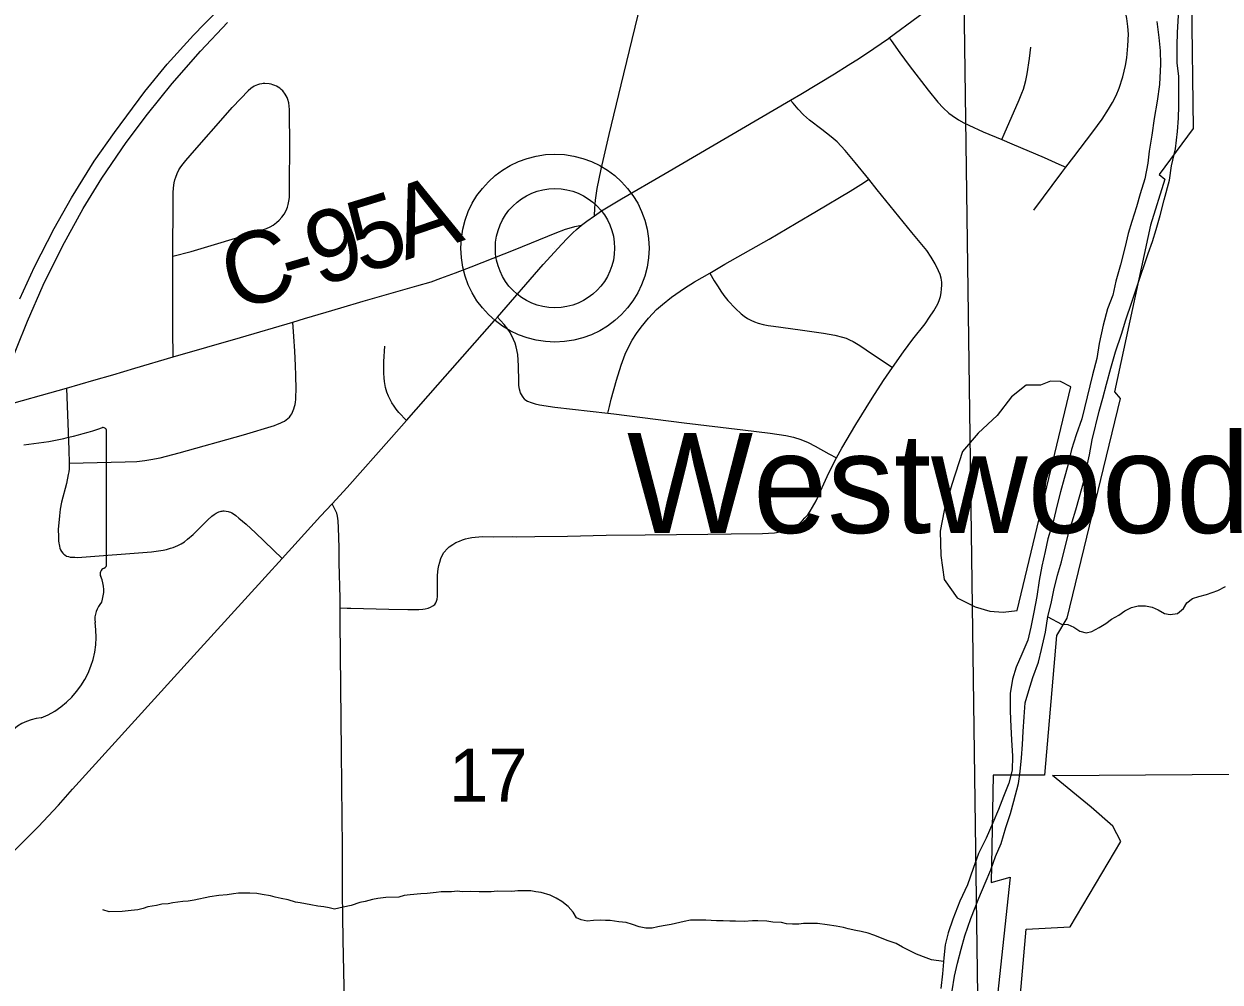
# Model space of a CAD drawing. Extents: x 0 to 34, y 0 to 22.
# Drawn here: x 7.165 to 8.111, y 18.473 to 19.232 of the extents above; entities that cross this region are included whole.
import ezdxf

# ---------------------------------------------------------------- set-up
doc = ezdxf.new("R2010")
doc.units = 0
for name, color, linetype in [('GM_X_County_Road', 7, 'Continuous'), ('GM_X_County_Road_Text', 7, 'Continuous'), ('GM_X_Major_River', 7, 'Continuous'), ('GM_X_Minor_Lake', 7, 'Continuous'), ('GM_X_Minor_River', 7, 'Continuous'), ('GM_X_Section', 7, 'Continuous'), ('GM_X_Section_Text', 7, 'Continuous'), ('GM_X_State_Route', 7, 'Continuous'), ('GM_X_State_Shield', 7, 'Continuous'), ('GM_X_Township_Road', 7, 'Continuous'), ('GM_X_Unincorporated', 7, 'Continuous'), ('GM_X_Unincorporated_Location', 7, 'Continuous'), ('GM_X_Unincorporated_Text', 7, 'Continuous')]:
    doc.layers.add(name, color=color, linetype=linetype)

msp = doc.modelspace()

# ---------------------------------------------------------------- linework, layer by layer
at = {"layer": 'GM_X_County_Road'}
msp.add_line((7.13975, 18.92718), (7.19837, 18.94339), dxfattribs=at)
for points in [[(7.61596, 19.07986), (7.61634, 19.08595), (7.61673, 19.09225), (7.61814, 19.10156), (7.62132, 19.11684), (7.62769, 19.14418), (7.63728, 19.18355), (7.65046, 19.23785), (7.65951, 19.27714)], [(7.8493, 19.2208), (7.87219, 19.23783), (7.90225, 19.25991), (7.91163, 19.26642), (7.92009, 19.2719), (7.92362, 19.27405)], [(7.77107, 19.17149), (7.77918, 19.17624), (7.80601, 19.19233), (7.81679, 19.19922), (7.82563, 19.20472), (7.83706, 19.21235), (7.84864, 19.22032), (7.8493, 19.2208)], [(7.61596, 19.07986), (7.62162, 19.08382), (7.63756, 19.09343), (7.67204, 19.11347), (7.77107, 19.17149)], [(7.60583, 19.07256), (7.6101, 19.07574), (7.61596, 19.07986)], [(7.37735, 18.99585), (7.38665, 18.99858), (7.40378, 19.0037), (7.41538, 19.00708), (7.43309, 19.01225), (7.47539, 19.02448), (7.48687, 19.0278), (7.49452, 19.03049), (7.5061, 19.0347), (7.51859, 19.03956), (7.55332, 19.05339), (7.58502, 19.06625), (7.5932, 19.06928), (7.59776, 19.07073), (7.60053, 19.07143), (7.60583, 19.07256)], [(7.53937, 18.99983), (7.57544, 19.04144), (7.5901, 19.05753), (7.59438, 19.06204), (7.59646, 19.06401), (7.59893, 19.06637), (7.60186, 19.06911), (7.60583, 19.07256)], [(7.28287, 18.96823), (7.336, 18.98369), (7.37735, 18.99585)], [(7.46732, 18.91785), (7.49216, 18.94611), (7.53698, 18.99707), (7.53937, 18.99983)], [(7.19837, 18.94339), (7.22009, 18.94977), (7.23495, 18.95406), (7.25249, 18.95937), (7.28287, 18.96823)], [(7.40851, 18.85201), (7.42041, 18.86491), (7.45543, 18.90433), (7.46732, 18.91785)], [(7.3689, 18.80869), (7.39939, 18.84211), (7.40851, 18.85201)], [(6.91432, 18.35384), (6.92169, 18.36116), (7.00322, 18.43572), (7.06045, 18.4882), (7.09027, 18.5154), (7.15409, 18.57432), (7.16355, 18.58378), (7.17608, 18.59615), (7.19198, 18.61337), (7.20324, 18.62595), (7.29913, 18.73183), (7.35546, 18.79395), (7.3689, 18.80869)]]:
    msp.add_lwpolyline(points, dxfattribs=at)
at = {"layer": 'GM_X_Major_River'}
for points in [[(7.89913, 18.46638), (7.90094, 18.47815), (7.90314, 18.48841), (7.90609, 18.49943), (7.90905, 18.51007), (7.91388, 18.52376), (7.92021, 18.53974), (7.92505, 18.55153), (7.92952, 18.56218), (7.93324, 18.57283), (7.93771, 18.5831), (7.94141, 18.59565), (7.94512, 18.60667), (7.94771, 18.61655), (7.9514, 18.63061), (7.95285, 18.6401), (7.95391, 18.65073), (7.95459, 18.66136), (7.95528, 18.6716), (7.95596, 18.68336), (7.95664, 18.69436), (7.9596, 18.70425), (7.96293, 18.71451), (7.9674, 18.72668), (7.9696, 18.73656), (7.97292, 18.75024), (7.97472, 18.76276), (7.9773, 18.77302), (7.9795, 18.78366), (7.98245, 18.79544), (7.98541, 18.80608), (7.98835, 18.81786), (7.99094, 18.82812), (7.99687, 18.84712), (7.99982, 18.85739), (8.00278, 18.86879), (8.00535, 18.8798), (8.00755, 18.89082), (8.00974, 18.90259), (8.01526, 18.92539), (8.01822, 18.93565), (8.02117, 18.94667), (8.0245, 18.95921), (8.0282, 18.97213), (8.03302, 18.9862), (8.03635, 18.9976), (8.04118, 19.01167), (8.04526, 19.02421), (8.05417, 19.05007), (8.05751, 19.05958), (8.06048, 19.06908), (8.06343, 19.0801), (8.06675, 19.09264), (8.07081, 19.10822), (8.07263, 19.11961), (8.07557, 19.13291), (8.07736, 19.14657), (8.07805, 19.1572), (8.07836, 19.16706), (8.0782, 19.19057), (8.07699, 19.2008), (8.07689, 19.21483), (8.0772, 19.22507), (8.07822, 19.24289)], [(8.06086, 19.23368), (8.06246, 19.22117), (8.06367, 19.21056), (8.06374, 19.19994), (8.06309, 19.18401), (8.06129, 19.17072), (8.05873, 19.15705), (8.05693, 19.14376), (8.05475, 19.13123), (8.05368, 19.12174), (8.05149, 19.10921), (8.04778, 19.09743), (8.04482, 19.08717), (8.04112, 19.07538), (8.03815, 19.06588), (8.03595, 19.05562), (8.03226, 19.04118), (8.02857, 19.02826)], [(8.02857, 19.02826), (8.02599, 19.01724), (8.0219, 19.00621), (8.01858, 18.9933), (8.01527, 18.97886), (8.01346, 18.96709), (8.01014, 18.95417), (8.00167, 18.91921), (7.99721, 18.90667), (7.9935, 18.89488), (7.99056, 18.88235), (7.9876, 18.87208), (7.98465, 18.86144), (7.9817, 18.85004), (7.97912, 18.83865), (7.97468, 18.8242), (7.97247, 18.81432), (7.9699, 18.80255), (7.96771, 18.79115), (7.9659, 18.77863), (7.96372, 18.76609), (7.96115, 18.75432), (7.95894, 18.74406), (7.9541, 18.73303), (7.94962, 18.72275), (7.94666, 18.71325), (7.94484, 18.70186), (7.94494, 18.68783), (7.94541, 18.67532), (7.94586, 18.66508), (7.9467, 18.65219), (7.9464, 18.64119), (7.94382, 18.63093), (7.93973, 18.62028), (7.93563, 18.61001), (7.93116, 18.59936), (7.92594, 18.58718), (7.91996, 18.575), (7.9155, 18.56321), (7.91105, 18.55029), (7.90507, 18.53735), (7.89949, 18.52327), (7.89578, 18.51225), (7.89357, 18.50275), (7.89251, 18.4925), (7.89146, 18.47998), (7.89003, 18.46821)]]:
    msp.add_lwpolyline(points, dxfattribs=at)
at = {"layer": 'GM_X_Minor_Lake'}
for points in [[(7.99278, 18.94456), (7.9848, 18.94867), (7.97685, 18.94899), (7.96891, 18.94589), (7.95755, 18.94581), (7.94588, 18.93662), (7.93462, 18.92175), (7.91956, 18.90798), (7.90716, 18.89347), (7.89863, 18.86724), (7.89272, 18.84672), (7.88942, 18.83039), (7.88993, 18.81105), (7.89271, 18.79211), (7.90304, 18.77739), (7.9171, 18.7703), (7.92887, 18.76697), (7.93948, 18.76629), (7.95045, 18.76751)], [(7.95045, 18.76751), (7.99278, 18.94456)]]:
    msp.add_lwpolyline(points, dxfattribs=at)
at = {"layer": 'GM_X_Minor_River'}
for points in [[(7.97468, 18.7625), (7.98559, 18.75672), (7.99053, 18.75641), (7.99513, 18.75419), (8.00011, 18.75121), (8.00507, 18.74976), (8.00962, 18.75096), (8.01529, 18.75407), (8.02057, 18.75718), (8.02509, 18.76066), (8.03075, 18.76378), (8.03565, 18.76726), (8.04094, 18.76999), (8.04625, 18.7712), (8.05196, 18.77128), (8.05729, 18.77021), (8.06189, 18.76799), (8.06687, 18.76502), (8.07144, 18.76432), (8.07714, 18.76516), (8.08203, 18.76902), (8.08463, 18.77361), (8.08915, 18.77709), (8.09408, 18.77868), (8.10014, 18.78028), (8.10923, 18.78344), (8.11527, 18.78655)], [(7.33039, 18.54324), (7.32546, 18.54241), (7.319, 18.54195), (7.31179, 18.54071), (7.29927, 18.53827), (7.29472, 18.53745), (7.29054, 18.53701), (7.28636, 18.53657), (7.28257, 18.53614), (7.27877, 18.53533), (7.27383, 18.53489), (7.26966, 18.53407), (7.26283, 18.53284), (7.25904, 18.53165), (7.25488, 18.53046), (7.24956, 18.53001), (7.24234, 18.52915), (7.23208, 18.52901), (7.22711, 18.53047)], [(7.89227, 18.48967), (7.88254, 18.49096), (7.87834, 18.49243), (7.8707, 18.49536), (7.86495, 18.49833), (7.8596, 18.50091), (7.85461, 18.50389), (7.8485, 18.50608), (7.83703, 18.51049), (7.83245, 18.51195), (7.8271, 18.5134), (7.82291, 18.5141), (7.81681, 18.51554), (7.81299, 18.51663), (7.80727, 18.51769), (7.80003, 18.51873), (7.79241, 18.51977), (7.78139, 18.51962), (7.77759, 18.5192), (7.77264, 18.51913), (7.76808, 18.51945), (7.76388, 18.52053), (7.75703, 18.52082), (7.75246, 18.52152), (7.74523, 18.5218), (7.74104, 18.52175), (7.73458, 18.52128), (7.72774, 18.52157), (7.72317, 18.52151), (7.71784, 18.52182), (7.71252, 18.52175), (7.70414, 18.52239), (7.69197, 18.52223), (7.68704, 18.52141), (7.6768, 18.51899), (7.67035, 18.51777), (7.66618, 18.51695), (7.66163, 18.51613), (7.65668, 18.51606), (7.65135, 18.51713), (7.646, 18.51896), (7.64103, 18.52041), (7.63532, 18.5211), (7.62846, 18.52214), (7.62466, 18.52209), (7.62085, 18.52242), (7.61515, 18.52197), (7.61021, 18.52152), (7.60564, 18.5226), (7.60181, 18.52407), (7.59909, 18.52859), (7.59523, 18.5331), (7.59023, 18.53721), (7.58564, 18.53981), (7.58104, 18.54202), (7.57379, 18.54421), (7.5696, 18.54491), (7.56578, 18.54562), (7.55552, 18.54548), (7.55058, 18.54504), (7.53916, 18.54527), (7.53423, 18.54482), (7.52472, 18.54469), (7.51825, 18.54499), (7.51141, 18.5449), (7.5076, 18.54522), (7.50304, 18.54478), (7.49467, 18.54467), (7.49088, 18.54424), (7.48366, 18.54339), (7.47872, 18.54332), (7.47036, 18.54245), (7.46542, 18.542), (7.46126, 18.54043), (7.45099, 18.54029), (7.44454, 18.53945), (7.44037, 18.53863), (7.43468, 18.53704), (7.43051, 18.53622), (7.42369, 18.53385), (7.41724, 18.53262), (7.41042, 18.53101), (7.40622, 18.5321), (7.40203, 18.5328), (7.39708, 18.53349), (7.39174, 18.53456), (7.38335, 18.53597), (7.37954, 18.53668), (7.37381, 18.5385), (7.36809, 18.53957), (7.36352, 18.54064), (7.3597, 18.54173), (7.35322, 18.54279), (7.34903, 18.54349), (7.34332, 18.54379), (7.33457, 18.54368), (7.33039, 18.54324)]]:
    msp.add_lwpolyline(points, dxfattribs=at)
at = {"layer": 'GM_X_Section'}
msp.add_lwpolyline([(6.90571, 19.27835), (7.90787, 19.27209), (7.92171, 18.27008), (6.91054, 18.26226)], close=True, dxfattribs=at)
at = {"layer": 'GM_X_State_Route'}
for points in [[(8.08837, 19.2499), (8.08968, 19.14892), (8.06277, 19.1126), (8.06736, 19.10888), (8.05588, 19.07263), (8.02743, 18.94064), (8.0318, 18.93533), (7.98984, 18.76153), (7.98148, 18.74759), (7.972, 18.63707), (7.93134, 18.63718), (7.92986, 18.55205), (7.94491, 18.55635), (7.91397, 18.26868)], [(7.16136, 19.0142), (7.17295, 19.03958), (7.18851, 19.06993), (7.20225, 19.09421), (7.22038, 19.1231), (7.23632, 19.146), (7.2604, 19.17833), (7.27812, 19.19985), (7.29888, 19.22285), (7.30729, 19.2316), (7.32045, 19.24476)], [(7.1501, 18.95335), (7.16747, 18.99664), (7.17997, 19.02514), (7.19521, 19.05579), (7.21169, 19.0858), (7.22646, 19.10961), (7.24569, 19.13792), (7.26235, 19.16044), (7.2819, 19.18464), (7.30448, 19.21033), (7.32582, 19.23296)], [(8.14525, 18.29824), (7.93841, 18.29467), (7.95755, 18.5152), (7.99225, 18.51719), (8.03233, 18.58473), (8.02624, 18.59679), (8.00889, 18.61168), (7.97843, 18.63678), (8.27306, 18.63894)]]:
    msp.add_lwpolyline(points, dxfattribs=at)
at = {"layer": 'GM_X_State_Shield'}
for p, q in [((7.23015, 18.80427), (7.23015, 18.90895)), ((7.23012, 18.80429), (7.23015, 18.80427))]:
    msp.add_line(p, q, dxfattribs=at)
for centre, radius, start, end in [((7.13623, 19.17682), 0.27962, 275.84447, 288.90645), ((7.22722, 18.90939), 0.00294, 351.86209, 97.738), ((7.22702, 18.80386), 0.00314, 289.60381, 7.73413), ((7.22947, 18.79658), 0.00454, 107.94398, 210.33697), ((7.20057, 18.78335), 0.02727, 340.03296, 23.64957), ((7.24066, 18.76046), 0.01984, 136.8065, 186.92959), ((7.15189, 18.74714), 0.06994, 292.30889, 8.98584), ((7.18138, 18.64425), 0.0383, 94.40312, 142.57675)]:
    msp.add_arc(centre, radius, start, end, dxfattribs=at)
at = {"layer": 'GM_X_Township_Road'}
for points in [[(7.98897, 19.11835), (7.99532, 19.12662), (8.0104, 19.1464), (8.01767, 19.15649), (8.0228, 19.16429), (8.02592, 19.16968), (8.0287, 19.17524), (8.03106, 19.18099), (8.03392, 19.18988), (8.03618, 19.19894), (8.03718, 19.20508), (8.03808, 19.21438), (8.03838, 19.2237), (8.03804, 19.22992), (8.03725, 19.23609), (8.03538, 19.24524), (8.03297, 19.25426), (8.03001, 19.26311), (8.01992, 19.28923), (8.01532, 19.30136), (8.01215, 19.30972), (8.01097, 19.31262)], [(7.8493, 19.2208), (7.85072, 19.21877), (7.85755, 19.20892), (7.8649, 19.199), (7.87995, 19.1794), (7.88779, 19.16986), (7.89197, 19.16533), (7.89649, 19.16113), (7.89892, 19.15924), (7.9041, 19.1559), (7.90829, 19.15352), (7.91228, 19.15156), (7.92353, 19.14649), (7.93832, 19.14029)], [(7.93832, 19.14029), (7.94018, 19.14455), (7.95206, 19.17181), (7.95408, 19.17701), (7.95532, 19.18011), (7.95615, 19.18296), (7.95737, 19.18701), (7.95844, 19.19224), (7.96007, 19.20442), (7.96125, 19.21355)], [(7.28263, 19.04787), (7.29692, 19.05181), (7.35054, 19.06772), (7.35354, 19.06873), (7.3566, 19.06988), (7.35943, 19.0712), (7.36191, 19.07261), (7.36463, 19.07473), (7.36668, 19.0766), (7.36881, 19.07886), (7.37064, 19.08136), (7.37213, 19.08408), (7.3733, 19.08671), (7.37386, 19.08882), (7.37433, 19.09148), (7.37469, 19.0944), (7.37483, 19.0971), (7.37482, 19.10105), (7.37498, 19.13965), (7.37487, 19.15829), (7.37473, 19.16405), (7.37454, 19.16671), (7.37414, 19.16949), (7.37356, 19.17189), (7.37286, 19.17357), (7.37139, 19.17631), (7.36951, 19.17878), (7.36832, 19.17992), (7.3672, 19.18086), (7.36586, 19.18167), (7.36455, 19.18246), (7.36307, 19.18316), (7.36167, 19.18362), (7.36022, 19.18407), (7.35865, 19.18437), (7.35525, 19.1846), (7.35406, 19.18466), (7.35292, 19.18453), (7.35109, 19.1842), (7.34956, 19.18374), (7.34805, 19.18316), (7.34672, 19.1825), (7.34411, 19.18081), (7.34199, 19.17899)], [(7.28263, 19.04787), (7.28264, 19.09206), (7.28274, 19.09844), (7.2829, 19.10192), (7.28317, 19.10421), (7.28357, 19.10614), (7.28404, 19.10829), (7.2848, 19.11055), (7.28598, 19.1135), (7.28734, 19.11625), (7.28888, 19.11866), (7.2906, 19.12102), (7.29288, 19.12383), (7.29619, 19.12769), (7.30514, 19.13789), (7.31864, 19.1532), (7.32954, 19.16564), (7.33633, 19.17293), (7.34199, 19.17899)], [(7.83303, 19.10888), (7.82236, 19.1222), (7.8144, 19.13173), (7.80798, 19.13845), (7.80331, 19.1425), (7.79592, 19.14818), (7.7861, 19.15577), (7.7815, 19.15991), (7.7773, 19.16445), (7.77312, 19.16917), (7.77107, 19.17149)], [(7.93832, 19.14029), (7.94629, 19.13695), (7.97175, 19.12598), (7.9835, 19.12077), (7.98897, 19.11835)], [(7.96358, 19.08431), (7.98585, 19.11429), (7.98897, 19.11835)], [(7.70726, 19.03466), (7.7193, 19.04159), (7.75433, 19.0615), (7.77569, 19.07411), (7.79168, 19.08364), (7.81842, 19.09934), (7.82881, 19.10613), (7.83303, 19.10888)], [(7.85194, 18.95993), (7.86059, 18.97234), (7.868, 18.98236), (7.87753, 18.99454), (7.88115, 18.99958), (7.88454, 19.00475), (7.88756, 19.01018), (7.88879, 19.013), (7.8897, 19.01594), (7.89031, 19.01897), (7.8907, 19.02206), (7.89086, 19.02514), (7.89075, 19.02745), (7.89024, 19.03046), (7.8894, 19.03345), (7.88831, 19.03635), (7.88561, 19.04194), (7.8825, 19.0473), (7.87896, 19.05238), (7.86723, 19.0668), (7.83981, 19.10041), (7.83303, 19.10888)], [(7.28287, 18.96823), (7.28255, 18.98918), (7.28263, 19.03287), (7.28263, 19.04787)], [(7.62672, 18.92363), (7.62795, 18.92885), (7.62938, 18.93489), (7.63339, 18.94987), (7.63708, 18.9617), (7.64034, 18.97042), (7.64292, 18.97606), (7.64588, 18.9815), (7.64922, 18.98672), (7.65292, 18.99171), (7.65887, 18.99886), (7.66524, 19.00565), (7.66979, 19.00985), (7.6771, 19.01559), (7.68727, 19.0227), (7.69513, 19.02767), (7.70726, 19.03466)], [(7.70726, 19.03466), (7.71081, 19.0284), (7.7138, 19.02365), (7.71613, 19.02032), (7.71846, 19.01696), (7.72149, 19.01294), (7.72761, 19.0065), (7.73213, 19.00233), (7.73455, 19.00044), (7.73711, 18.99875), (7.73981, 18.99728), (7.74263, 18.99606), (7.74554, 18.99508), (7.74945, 18.99386), (7.75339, 18.9932), (7.75755, 18.99262), (7.77886, 18.9898), (7.7971, 18.98715), (7.80617, 18.98544), (7.81215, 18.98399), (7.81506, 18.98302), (7.81788, 18.98184), (7.82062, 18.98046), (7.8259, 18.97731), (7.83608, 18.97044), (7.84691, 18.96326), (7.85194, 18.95993)], [(7.20051, 18.88416), (7.24478, 18.88508), (7.25407, 18.88552), (7.26028, 18.88618), (7.26522, 18.88691), (7.27253, 18.88831), (7.28758, 18.89222), (7.33853, 18.90655), (7.36292, 18.914), (7.36539, 18.91491), (7.36735, 18.91569), (7.36908, 18.91652), (7.37087, 18.9175), (7.37224, 18.91848), (7.37348, 18.91949), (7.37476, 18.92066), (7.37592, 18.92223), (7.37656, 18.92324), (7.37723, 18.92455), (7.37825, 18.92726), (7.37884, 18.92907), (7.37918, 18.93047), (7.37958, 18.93242), (7.37982, 18.93446), (7.37987, 18.93642), (7.37999, 18.9428), (7.3798, 18.9535), (7.37959, 18.96152), (7.3791, 18.97271), (7.37825, 18.98432), (7.37735, 18.99585)], [(7.56108, 18.93464), (7.55911, 18.93712), (7.55758, 18.93978), (7.55675, 18.9427), (7.55634, 18.94573), (7.55612, 18.94879), (7.5559, 18.96116), (7.55529, 18.97026), (7.55417, 18.97624), (7.55325, 18.97917), (7.55207, 18.98201), (7.5493, 18.98751), (7.54762, 18.99008), (7.5447, 18.9939), (7.54173, 18.99719), (7.53937, 18.99983)], [(7.46732, 18.91785), (7.46135, 18.92423), (7.45921, 18.927), (7.45754, 18.92933), (7.45582, 18.93188), (7.4543, 18.93456), (7.45309, 18.93727), (7.45189, 18.94025), (7.45118, 18.94227), (7.45072, 18.94396), (7.4504, 18.94559), (7.44992, 18.94875), (7.44962, 18.9516), (7.44941, 18.95537), (7.44934, 18.96454), (7.45031, 18.97663)], [(7.80753, 18.88824), (7.8117, 18.89593), (7.82289, 18.91473), (7.83583, 18.93559), (7.8448, 18.94969), (7.85194, 18.95993)], [(7.19837, 18.94339), (7.20031, 18.89475), (7.20051, 18.88416)], [(7.56108, 18.93464), (7.56308, 18.93333), (7.5659, 18.93206), (7.56919, 18.93108), (7.57246, 18.93034), (7.5848, 18.92854), (7.62672, 18.92363)], [(7.62672, 18.92363), (7.63125, 18.92309), (7.6869, 18.91598), (7.73336, 18.9105), (7.75503, 18.90787), (7.76735, 18.90603), (7.77343, 18.90467), (7.77937, 18.90282), (7.78512, 18.90047), (7.79068, 18.89768), (7.80154, 18.89159), (7.80753, 18.88824)], [(7.48965, 18.77227), (7.4905, 18.77351), (7.49117, 18.77488), (7.49156, 18.77635), (7.49183, 18.77866), (7.49187, 18.78437), (7.49189, 18.78758), (7.49184, 18.7928), (7.49182, 18.79542), (7.4923, 18.80039), (7.49288, 18.80304), (7.4936, 18.80582), (7.4946, 18.80871), (7.4959, 18.81147), (7.49696, 18.8133), (7.4998, 18.81667), (7.501, 18.81778), (7.50391, 18.8198), (7.50647, 18.82142), (7.50917, 18.82249), (7.51172, 18.82356), (7.51396, 18.82427), (7.51629, 18.82479), (7.51895, 18.82527), (7.52173, 18.82567), (7.52457, 18.8259), (7.52754, 18.82598), (7.5364, 18.82592), (7.55119, 18.82605), (7.5543, 18.8259), (7.56897, 18.82595), (7.59468, 18.82643), (7.62526, 18.82703), (7.65619, 18.82746), (7.6809, 18.82767), (7.70563, 18.82798), (7.72422, 18.82814), (7.74905, 18.8284), (7.75835, 18.82896), (7.76448, 18.82993), (7.76747, 18.83077), (7.77035, 18.83188), (7.77305, 18.83304), (7.77552, 18.83452), (7.77815, 18.83649), (7.78061, 18.83863), (7.78259, 18.84076), (7.78473, 18.84323), (7.7867, 18.84619), (7.78851, 18.84932), (7.79131, 18.85441), (7.79756, 18.86773), (7.80003, 18.87365), (7.80429, 18.8823), (7.80753, 18.88824)], [(7.20051, 18.88416), (7.2005, 18.8823), (7.20042, 18.8797), (7.20014, 18.8773), (7.19981, 18.87504), (7.1985, 18.86804), (7.19441, 18.85313), (7.19333, 18.8476), (7.19272, 18.84237), (7.19221, 18.83689), (7.19188, 18.83186), (7.19192, 18.8259), (7.1921, 18.8227), (7.19234, 18.82091), (7.19249, 18.8197), (7.19275, 18.81829), (7.19315, 18.81684), (7.19359, 18.8156), (7.19433, 18.81424), (7.19538, 18.81297), (7.19617, 18.81221), (7.19706, 18.81145), (7.19846, 18.81061), (7.19995, 18.81014), (7.20122, 18.80982), (7.20268, 18.80961), (7.205, 18.80961), (7.20721, 18.80956), (7.26571, 18.81405), (7.27482, 18.81529), (7.27753, 18.81584), (7.28072, 18.81672), (7.28287, 18.81748), (7.28637, 18.81889), (7.28902, 18.82027), (7.2916, 18.82188), (7.2942, 18.82396), (7.29866, 18.82765), (7.30671, 18.83579), (7.31022, 18.83931), (7.31333, 18.84205), (7.3151, 18.84341), (7.31684, 18.84465), (7.31772, 18.84513), (7.31891, 18.84565), (7.31986, 18.84593), (7.32085, 18.84615), (7.32156, 18.84623), (7.32226, 18.84632)], [(7.41482, 18.76959), (7.41479, 18.77718), (7.41406, 18.80516), (7.41408, 18.8145), (7.41399, 18.81744), (7.41354, 18.83288), (7.41319, 18.8385), (7.41273, 18.84221), (7.41218, 18.8445), (7.41154, 18.84623), (7.4099, 18.84935), (7.40851, 18.85201)], [(7.32226, 18.84632), (7.32308, 18.84631), (7.32481, 18.8462), (7.32617, 18.84594), (7.32707, 18.84569), (7.32804, 18.84535), (7.32918, 18.84481), (7.33046, 18.844), (7.33225, 18.84276), (7.33477, 18.84068), (7.34058, 18.83575), (7.34794, 18.82898), (7.3689, 18.80869)], [(7.41482, 18.76959), (7.42036, 18.76935), (7.42333, 18.76922), (7.45338, 18.76857), (7.46852, 18.7682), (7.47719, 18.76831), (7.48014, 18.76846), (7.48222, 18.76876), (7.48447, 18.76931), (7.48646, 18.77007), (7.4882, 18.77109), (7.48965, 18.77227)], [(7.4214, 18.22639), (7.42091, 18.23978), (7.42021, 18.26456), (7.41994, 18.28319), (7.41985, 18.30183), (7.41981, 18.30805), (7.41978, 18.31116), (7.41936, 18.34222), (7.41911, 18.36396), (7.41894, 18.38571), (7.41829, 18.44164), (7.41793, 18.4696), (7.41733, 18.50682), (7.41709, 18.52548), (7.41684, 18.54412), (7.41671, 18.55965), (7.41675, 18.58139), (7.41649, 18.60313), (7.41593, 18.65596), (7.41486, 18.75853), (7.41482, 18.76959)]]:
    msp.add_lwpolyline(points, dxfattribs=at)
at = {"layer": 'GM_X_Unincorporated'}
msp.add_lwpolyline([(8.9, 18.27692), (8.9, 19.27567), (7.90787, 19.27209), (7.92171, 18.27008)], close=True, dxfattribs=at)
for radius in [0.0744, 0.04716]:
    msp.add_circle((7.5848, 19.05435), radius, dxfattribs=at)
at = {"layer": 'GM_X_Unincorporated_Location'}
msp.add_line((7.5848, 19.05435), (7.5848, 19.05435), dxfattribs=at)

# ---------------------------------------------------------------- texts
at = {"layer": 'GM_X_County_Road_Text'}
for s, rotation, p in [('A', 18.89608, (7.46656, 19.04461)), ('5', 17.07829, (7.43149, 19.03381)), ('9', 16.3353, (7.3974, 19.02381)), ('C', 16.30397, (7.33072, 19.00431)), ('-', 16.30395, (7.37518, 19.01731))]:
    msp.add_text(s, height=0.05682, rotation=rotation, dxfattribs=at).set_placement(p)
at = {"layer": 'GM_X_Section_Text'}
msp.add_text('17', height=0.041856, rotation=0.00001, dxfattribs=at).set_placement((7.50098, 18.61621))
at = {"layer": 'GM_X_Unincorporated_Text'}
msp.add_text('Westwood', height=0.078977, rotation=0.00001, dxfattribs=at).set_placement((7.64182, 18.82891))

doc.saveas('drawing.dxf')
